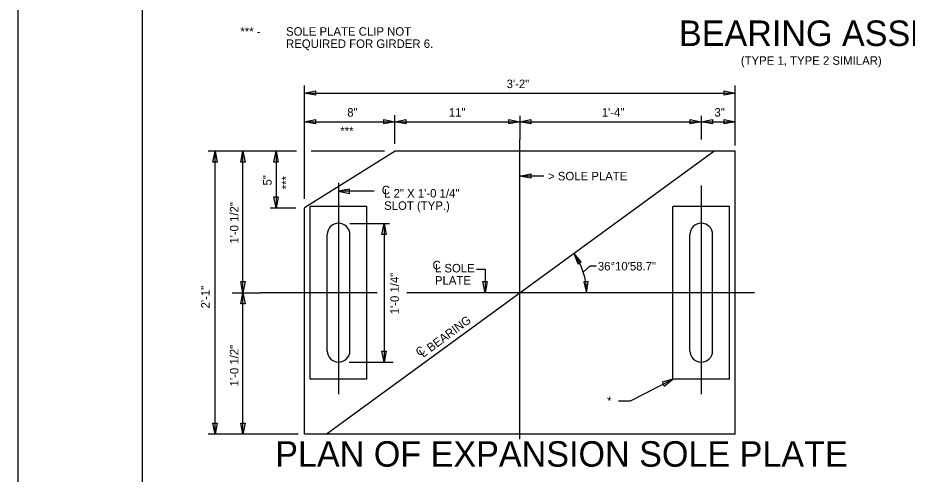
# Model space of a CAD drawing. Extents: x -125.5 to -89.4, y -5.1 to 16.9.
# Drawn here: x -125.53 to -112.46, y 3.64 to 10.36 of the extents above; entities that cross this region are included whole.
import ezdxf

# ---------------------------------------------------------------- set-up
doc = ezdxf.new("R2010")
doc.units = 0
for name, color, linetype in [('BR_AUTO DIMENSION', 7, 'Continuous'), ('BR_BORDER LINES', 7, 'Continuous'), ('BR_CENTER LINES', 7, 'Continuous'), ('BR_STRUCTURAL STEEL', 7, 'Continuous'), ('BR_TEXT', 7, 'Continuous'), ('Level 31', 7, 'Continuous')]:
    doc.layers.add(name, color=color, linetype=linetype)

msp = doc.modelspace()

# ---------------------------------------------------------------- linework, layer by layer
at = {"layer": 'BR_AUTO DIMENSION'}
for p, q in [((-121.317, 7.695), (-121.317, 9.364)), ((-114.984, 8.482), (-114.984, 9.364)), ((-121.317, 9.253), (-114.984, 9.253)), ((-119.988, 8.504), (-119.988, 8.929)), ((-118.151, 8.917), (-118.151, 8.57)), ((-115.484, 8.917), (-115.484, 8.57)), ((-121.317, 8.831), (-118.151, 8.831)), ((-118.151, 8.831), (-114.984, 8.831)), ((-121.433, 8.398), (-122.735, 8.398)), ((-122.633, 4.231), (-122.633, 8.398)), ((-122.223, 4.231), (-122.223, 8.398)), ((-121.736, 8.398), (-121.736, 7.561)), ((-120.143, 8.398), (-121.22, 8.398)), ((-117.797, 8.031), (-118.151, 8.031)), ((-120.293, 7.808), (-120.817, 7.808)), ((-121.447, 7.561), (-121.821, 7.561)), ((-120.653, 7.335), (-120.07, 7.335)), ((-120.148, 7.335), (-120.148, 5.294)), ((-117.219, 6.619), (-117.118, 6.71)), ((-117.118, 6.71), (-117.029, 6.71)), ((-118.788, 6.663), (-118.663, 6.663)), ((-118.663, 6.663), (-118.662, 6.314)), ((-122.383, 6.314), (-121.96, 6.314)), ((-120.663, 5.294), (-120.012, 5.294)), ((-116.523, 4.723), (-115.901, 5.044)), ((-116.701, 4.723), (-116.523, 4.723)), ((-121.411, 4.231), (-122.735, 4.231))]:
    msp.add_line(p, q, dxfattribs=at)
for points in [[(-121.155, 9.222), (-121.317, 9.253), (-121.155, 9.285)], [(-115.146, 9.285), (-114.984, 9.253), (-115.146, 9.222)], [(-121.155, 8.8), (-121.317, 8.831), (-121.155, 8.863)], [(-120.151, 8.863), (-119.988, 8.831), (-120.151, 8.8)], [(-119.826, 8.8), (-119.988, 8.831), (-119.826, 8.863)], [(-118.313, 8.863), (-118.151, 8.831), (-118.313, 8.8)], [(-117.988, 8.8), (-118.151, 8.831), (-117.988, 8.863)], [(-115.646, 8.863), (-115.484, 8.831), (-115.646, 8.8)], [(-115.321, 8.8), (-115.484, 8.831), (-115.321, 8.863)], [(-115.146, 8.863), (-114.984, 8.831), (-115.146, 8.8)], [(-122.665, 8.235), (-122.633, 8.398), (-122.602, 8.235)], [(-122.254, 8.235), (-122.223, 8.398), (-122.192, 8.235)], [(-121.767, 8.235), (-121.736, 8.398), (-121.705, 8.235)], [(-117.988, 8), (-118.151, 8.031), (-117.988, 8.062)], [(-121.705, 7.724), (-121.736, 7.561), (-121.767, 7.724)], [(-120.655, 7.839), (-120.817, 7.808), (-120.655, 7.777)], [(-120.179, 7.173), (-120.148, 7.335), (-120.117, 7.173)], [(-117.248, 6.771), (-117.358, 6.894), (-117.301, 6.738)], [(-122.192, 6.477), (-122.223, 6.314), (-122.254, 6.477)], [(-118.631, 6.477), (-118.662, 6.314), (-118.694, 6.477)], [(-117.211, 6.474), (-117.171, 6.313), (-117.148, 6.477)], [(-122.254, 6.152), (-122.223, 6.314), (-122.192, 6.152)], [(-120.117, 5.456), (-120.148, 5.294), (-120.179, 5.456)], [(-116.031, 4.941), (-115.901, 5.044), (-116.059, 4.997)], [(-122.602, 4.394), (-122.633, 4.231), (-122.665, 4.394)], [(-122.192, 4.394), (-122.223, 4.231), (-122.254, 4.394)]]:
    msp.add_lwpolyline(points, close=True, dxfattribs=at)
msp.add_arc((-118.165, 6.313), 0.994, 0, 35.8148, dxfattribs=at)
at = {"layer": 'BR_BORDER LINES'}
msp.add_line((-123.699, -4.566), (-123.699, 16.434), dxfattribs=at)
at = {"layer": 'BR_CENTER LINES'}
for p, q in [((-118.151, 6.314), (-118.151, 8.57)), ((-120.999, 4.231), (-115.302, 8.398)), ((-120.817, 7.932), (-120.817, 4.823)), ((-115.484, 7.893), (-115.484, 4.823)), ((-120.248, 6.314), (-121.96, 6.314)), ((-118.151, 6.314), (-119.814, 6.314)), ((-118.151, 4.158), (-118.151, 6.314)), ((-114.704, 6.314), (-118.151, 6.314))]:
    msp.add_line(p, q, dxfattribs=at)
at = {"layer": 'BR_STRUCTURAL STEEL'}
for p, q in [((-119.984, 8.398), (-121.317, 7.564)), ((-114.984, 8.398), (-119.984, 8.398)), ((-114.984, 4.231), (-114.984, 8.398)), ((-121.234, 5.044), (-121.234, 7.585)), ((-120.401, 7.585), (-121.234, 7.585)), ((-120.401, 5.044), (-120.401, 7.585)), ((-115.901, 5.044), (-115.901, 7.585)), ((-115.067, 7.585), (-115.901, 7.585)), ((-115.067, 5.044), (-115.067, 7.585)), ((-121.317, 4.231), (-121.317, 7.564)), ((-120.984, 5.46), (-120.984, 7.169)), ((-120.651, 5.46), (-120.651, 7.169)), ((-115.651, 5.46), (-115.651, 7.169)), ((-115.317, 5.46), (-115.317, 7.169)), ((-120.401, 5.044), (-121.234, 5.044)), ((-115.067, 5.044), (-115.901, 5.044)), ((-114.984, 4.231), (-121.317, 4.231))]:
    msp.add_line(p, q, dxfattribs=at)
for centre, start, end in [((-120.817, 7.169), 0, 180), ((-115.484, 7.169), 0, 180), ((-120.817, 5.46), 180, 0), ((-115.484, 5.46), 180, 0)]:
    msp.add_arc(centre, 0.167, start, end, dxfattribs=at)
at = {"layer": 'Level 31'}
msp.add_lwpolyline([(-125.533, -5.066), (-89.533, -5.066), (-89.533, 16.934), (-125.533, 16.934)], close=True, dxfattribs=at)

# ---------------------------------------------------------------- texts
at = {"layer": 'BR_AUTO DIMENSION'}
msp.add_text('(TYPE 1, TYPE 2 SIMILAR)', height=0.125, dxfattribs=at).set_placement((-114.903, 9.669))
at = {"layer": 'BR_TEXT'}
for s, height, rotation, p in [('*** -', 0.125, 360, (-122.26, 10.097)), ('SOLE PLATE CLIP NOT ', 0.125, 360, (-121.589, 10.097)), ('REQUIRED FOR GIRDER 6.', 0.125, 360, (-121.589, 9.917)), ('***', 0.125, 360, (-120.792, 8.634)), ('5"', 0.125, 90, (-121.801, 7.892)), ('***', 0.125, 90, (-121.528, 7.837)), ('> SOLE PLATE', 0.125, 360, (-117.737, 7.968)), ('C', 0.125, 0, (-120.181, 7.762)), ('L 2" X 1\'-0 1/4"', 0.125, 0, (-120.147, 7.715)), ('1\'-0 1/2"', 0.125, 90, (-122.289, 7.036)), ('SLOT (TYP.)', 0.125, 0, (-120.147, 7.534)), ('C', 0.125, 360, (-119.434, 6.658)), ('L SOLE ', 0.125, 360, (-119.4, 6.613)), ('36%%D10\'58.7"', 0.12497, 360, (-117.005, 6.642)), ('1\'-0 1/4"', 0.125, 90, (-119.931, 5.997)), ('PLATE', 0.125, 360, (-119.4, 6.433)), ('2\'-1"', 0.125, 90, (-122.712, 6.083)), ('L BEARING', 0.125, 36.6296, (-119.572, 5.354)), ('1\'-0 1/2"', 0.125, 90, (-122.289, 4.936)), ('C', 0.125, 36.6296, (-119.626, 5.37)), ('*', 0.125, 0, (-116.869, 4.662))]:
    msp.add_text(s, height=height, rotation=rotation, dxfattribs=at).set_placement(p)
for s, height, p in [('BEARING ASSEMBLY', 0.375, (-115.812, 9.946)), ('3\'-2"', 0.125, (-118.346, 9.326)), ('8"', 0.125, (-120.689, 8.906)), ('11"', 0.125, (-119.195, 8.906)), ('1\'-4"', 0.125, (-116.947, 8.906)), ('3"', 0.125, (-115.291, 8.906)), ('PLAN OF EXPANSION SOLE PLATE', 0.375, (-121.748, 3.754))]:
    msp.add_text(s, height=height, dxfattribs=at).set_placement(p)

doc.saveas('drawing.dxf')
